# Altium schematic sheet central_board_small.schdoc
size 276 x 117 mm
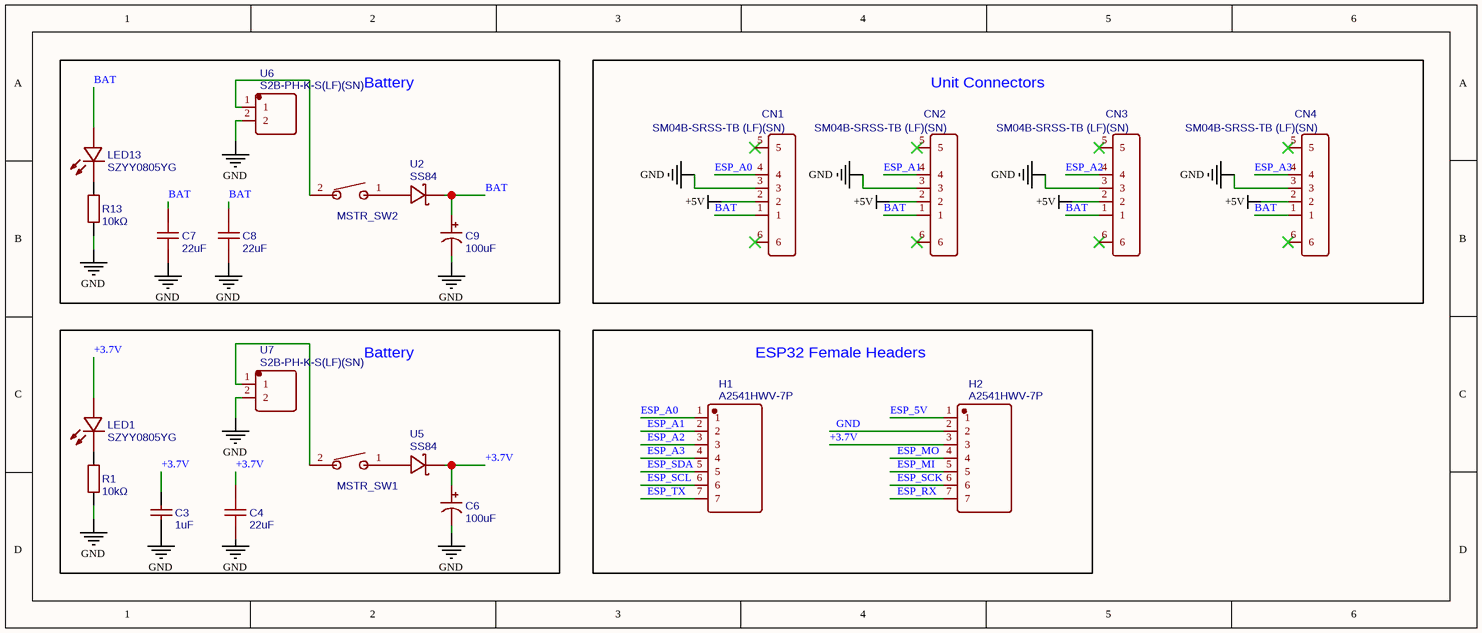
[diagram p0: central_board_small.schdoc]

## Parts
C3  1uF  [C0805]
C4  22uF  [C0805]
C6  100uF  [CAP-SMD_BD5.0-L5.3-W5.3-RD]
C7  22uF  [C0805]
C8  22uF  [C0805]
C9  100uF  [CAP-SMD_BD5.0-L5.3-W5.3-RD]
CN1  SM04B-SRSS-TB (LF)(SN)  [CONN-SMD_4P-P1.00_SM04B-SRSS-TB-LF-SN]
CN2  SM04B-SRSS-TB (LF)(SN)  [CONN-SMD_4P-P1.00_SM04B-SRSS-TB-LF-SN]
CN3  SM04B-SRSS-TB (LF)(SN)  [CONN-SMD_4P-P1.00_SM04B-SRSS-TB-LF-SN]
CN4  SM04B-SRSS-TB (LF)(SN)  [CONN-SMD_4P-P1.00_SM04B-SRSS-TB-LF-SN]
H1  A2541HWV-7P  [HDR-TH_7P-P2.54-V_A2541HWV-7P]
H2  A2541HWV-7P  [HDR-TH_7P-P2.54-V_A2541HWV-7P]
LED1  SZYY0805YG  [LED0805-R-RD_GREEN]
LED13  SZYY0805YG  [LED0805-R-RD_GREEN]
MSTR_SW1  RS601HL-1010011BB  [SW-TH_RS601HL-1010011BB]  (value not drawn)
MSTR_SW2  RS601HL-1010011BB  [SW-TH_RS601HL-1010011BB]  (value not drawn)
R1  10kΩ  [R0805]
R13  10kΩ  [R0805]
U2  SS84  [SMC_L6.9-W5.9-LS7.9-RD]
U5  SS84  [SMC_L6.9-W5.9-LS7.9-RD]
U6  S2B-PH-K-S(LF)(SN)  [CONN-TH_S2B-PH-K-S-LF-SN]
U7  S2B-PH-K-S(LF)(SN)  [CONN-TH_S2B-PH-K-S-LF-SN]

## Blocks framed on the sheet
Battery: C7-C9 LED13 MSTR_SW2 R13 U2 U6
Unit Connectors: CN1-CN4
Battery: C3 C4 C6 LED1 MSTR_SW1 R1 U5 U7
ESP32 Female Headers: H1 H2

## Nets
+5V: CN1.2 CN2.2 CN3.2 CN4.2
GND: C3.1 C4.1 C6.2 C7.1 C8.1 C9.2 CN1.3 CN2.3 CN3.3 CN4.3 H2.2 R1.1 R13.1 U6.2 U7.2
+3.7V: C3.2 C4.2 C6.1 H2.3 LED1.1(+) U5.1(K)
BAT: C7.2 C8.2 C9.1 CN1.1 CN2.1 CN3.1 CN4.1 LED13.1(+) U2.1(K)
ESP_5V: H2.1
ESP_A0: CN1.4 H1.1
ESP_A1: CN2.4 H1.2
ESP_A2: CN3.4 H1.3
ESP_A3: CN4.4 H1.4
ESP_MI: H2.5
ESP_MO: H2.4
ESP_RX: H2.7
ESP_SCK: H2.6
ESP_SCL: H1.6
ESP_SDA: H1.5
ESP_TX: H1.7
NetLED1_2: LED1.2(-) R1.2
NetLED13_2: LED13.2(-) R13.2
NetMSTR_SW1_1: MSTR_SW1.1 U5.2(A)
NetMSTR_SW1_2: MSTR_SW1.2 U7.1
NetMSTR_SW2_1: MSTR_SW2.1 U2.2(A)
NetMSTR_SW2_2: MSTR_SW2.2 U6.1

Not connected (* = marked no-connect by the designer): CN1 5* 6*; CN2 5* 6*; CN3 5* 6*; CN4 5* 6*

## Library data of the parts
C3 = 1uF: Manufacturer Part: CL21B105KBFNNNE; Manufacturer: SAMSUNG(三星); nameAlias: Capacitance
C4 C7 C8 = 22uF: Manufacturer: SAMSUNG(三星); Manufacturer Part: CL21A226MAYNNNE; nameAlias: Capacitance; Contributor: LCSC
C6 C9 = 100uF: Manufacturer: ST(先科); Manufacturer Part: CS1A101M-CRD54; nameAlias: Capacitance
CN1-CN4 = SM04B-SRSS-TB (LF)(SN): Manufacturer: JST; Contributor: LCSC
H1 H2 = A2541HWV-7P: Manufacturer: CJT(长江连接器); Contributor: LCSC
LED1 LED13 = SZYY0805YG: Manufacturer: yongyu(永裕光电); Contributor: LCSC
MSTR_SW1 MSTR_SW2 = RS601HL-1010011BB: Manufacturer: HCTL(华灿天禄); Contributor: lcsc
R1 R13 = 10kΩ: Manufacturer: UNI-ROYAL(厚声); Manufacturer Part: 0805W8F1002T5E; nameAlias: Resistance; Resistance (Ohms): 10K
U2 U5 = SS84: Manufacturer: GOODWORK(固得沃克); Contributor: lcsc
U6 U7 = S2B-PH-K-S(LF)(SN): Manufacturer: JST; Contributor: LCSC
